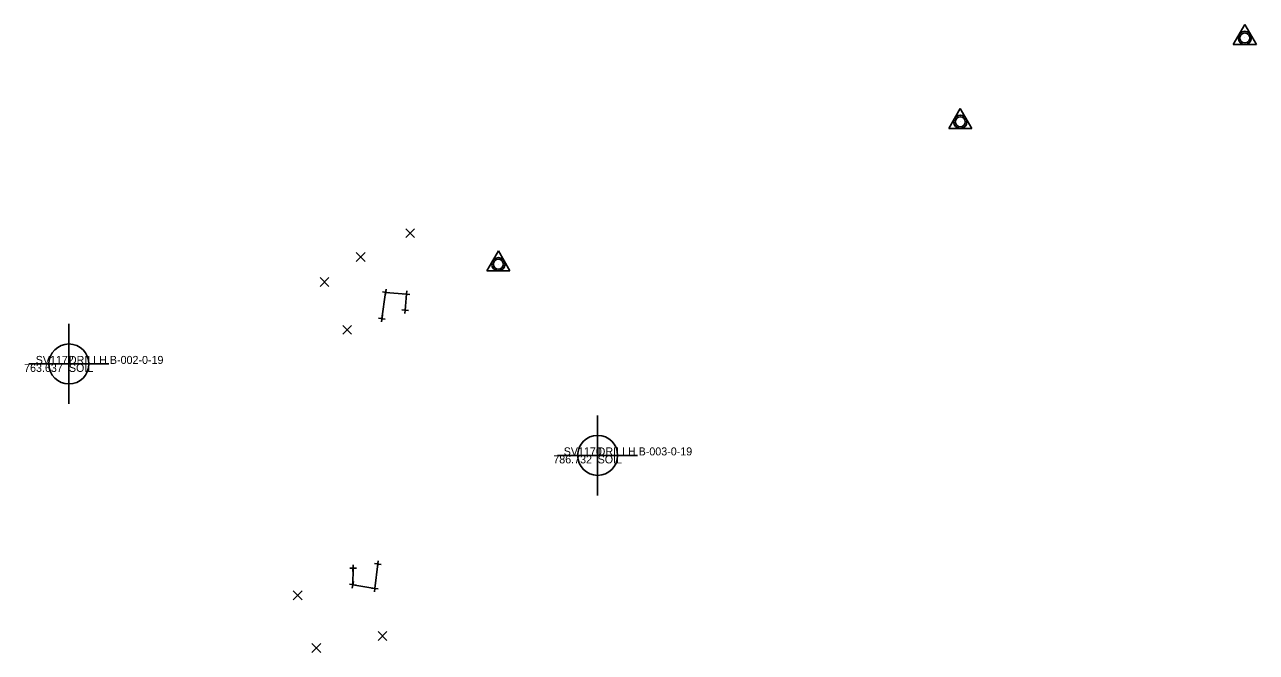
# Model space of a CAD drawing. Extents: x 1543088 to 1543675, y 586989 to 588001.
# Drawn here: x 1543273.7 to 1543458.4, y 587383.2 to 587477.5 of the extents above; entities that cross this region are included whole.
import ezdxf

# ---------------------------------------------------------------- set-up
doc = ezdxf.new("R2010")
doc.units = 0
for name, color, linetype in [('GT_Project_Soil_Boring', 7, 'Continuous'), ('SV_Control_Point', 7, 'Continuous'), ('SV_X_Break_Lines', 7, 'Continuous'), ('SV_X_Control_Cells_Found', 7, 'Continuous'), ('SV_X_Random_Point', 7, 'Continuous'), ('SV_X_Shot_Marker', 7, 'Continuous'), ('SV_X_Text_Comment', 7, 'Continuous'), ('SV_X_Text_Description', 7, 'Continuous'), ('SV_X_Text_Elevation', 7, 'Continuous'), ('SV_X_Text_Name', 7, 'Continuous')]:
    doc.layers.add(name, color=color, linetype=linetype)

msp = doc.modelspace()

# ---------------------------------------------------------------- linework, layer by layer
at = {"layer": 'GT_Project_Soil_Boring'}
for p, q in [((1543280.33, 587426.54), (1543280.33, 587432.54)), ((1543280.33, 587429.54), (1543280.33, 587426.54)), ((1543280.33, 587426.54), (1543274.33, 587426.54)), ((1543280.33, 587426.54), (1543277.33, 587426.54)), ((1543280.33, 587426.54), (1543280.33, 587420.54)), ((1543280.33, 587426.54), (1543286.33, 587426.54)), ((1543280.33, 587423.54), (1543280.33, 587426.54)), ((1543280.33, 587426.54), (1543283.33, 587426.54)), ((1543359.64, 587412.81), (1543359.64, 587418.81)), ((1543359.64, 587415.81), (1543359.64, 587412.81)), ((1543359.64, 587412.81), (1543353.64, 587412.81)), ((1543359.64, 587412.81), (1543356.64, 587412.81)), ((1543359.64, 587412.81), (1543359.64, 587406.81)), ((1543359.64, 587412.81), (1543365.64, 587412.81)), ((1543359.64, 587409.81), (1543359.64, 587412.81)), ((1543359.64, 587412.81), (1543362.64, 587412.81))]:
    msp.add_line(p, q, dxfattribs=at)
for centre in [(1543280.33, 587426.54), (1543359.64, 587412.81)]:
    msp.add_circle(centre, 3, dxfattribs=at)
for centre, start, end in [((1543280.33, 587426.54), 90, 180), ((1543280.33, 587426.54), 270, 360), ((1543359.64, 587412.81), 90, 180), ((1543359.64, 587412.81), 270, 360)]:
    msp.add_arc(centre, 3, start, end, dxfattribs=at)
at = {"layer": 'SV_Control_Point'}
for p, q in [((1543454.98, 587474.46), (1543456.72, 587477.46)), ((1543456.72, 587477.46), (1543458.45, 587474.46)), ((1543458.45, 587474.46), (1543454.98, 587474.46)), ((1543456.72, 587475.46), (1543456.72, 587475.46)), ((1543412.3, 587461.88), (1543414.04, 587464.88)), ((1543414.04, 587464.88), (1543415.77, 587461.88)), ((1543414.04, 587462.88), (1543414.04, 587462.88)), ((1543415.77, 587461.88), (1543412.3, 587461.88)), ((1543343.01, 587440.51), (1543344.75, 587443.51)), ((1543344.75, 587443.51), (1543346.48, 587440.51)), ((1543346.48, 587440.51), (1543343.01, 587440.51)), ((1543344.75, 587441.51), (1543344.75, 587441.51))]:
    msp.add_line(p, q, dxfattribs=at)
for centre in [(1543456.72, 587475.46), (1543414.04, 587462.88), (1543344.75, 587441.51)]:
    msp.add_circle(centre, 1, dxfattribs=at)
at = {"layer": 'SV_X_Break_Lines'}
for points in [[(1543327.28, 587433.35), (1543327.84, 587437.27), (1543330.96, 587436.99), (1543330.77, 587434.6)], [(1543326.67, 587396.52), (1543326.23, 587392.85), (1543322.93, 587393.4), (1543322.95, 587395.89)]]:
    msp.add_lwpolyline(points, dxfattribs=at)
at = {"layer": 'SV_X_Control_Cells_Found'}
for centre in [(1543456.72, 587475.46), (1543414.04, 587462.88), (1543344.75, 587441.51)]:
    msp.add_circle(centre, 0.75, dxfattribs=at)
at = {"layer": 'SV_X_Random_Point'}
for p, q in [((1543330.85, 587445.49), (1543332.18, 587446.83)), ((1543330.85, 587446.83), (1543332.18, 587445.49)), ((1543323.42, 587441.91), (1543324.76, 587443.25)), ((1543323.42, 587443.25), (1543324.76, 587441.91)), ((1543318, 587438.16), (1543319.34, 587439.49)), ((1543318, 587439.49), (1543319.34, 587438.16)), ((1543321.4, 587431), (1543322.74, 587432.33)), ((1543321.4, 587432.33), (1543322.74, 587431)), ((1543313.98, 587391.16), (1543315.32, 587392.49)), ((1543313.98, 587392.49), (1543315.32, 587391.16)), ((1543326.71, 587385.03), (1543328.04, 587386.37)), ((1543326.71, 587386.37), (1543328.04, 587385.03)), ((1543316.76, 587383.25), (1543318.1, 587384.58)), ((1543316.76, 587384.58), (1543318.1, 587383.25))]:
    msp.add_line(p, q, dxfattribs=at)
at = {"layer": 'SV_X_Shot_Marker'}
for p, q in [((1543327.35, 587437.34), (1543328.34, 587437.2)), ((1543327.77, 587436.78), (1543327.91, 587437.77)), ((1543327.84, 587437.27), (1543327.84, 587437.27)), ((1543330.46, 587437.04), (1543331.45, 587436.95)), ((1543331, 587437.49), (1543330.91, 587436.49)), ((1543330.96, 587436.99), (1543330.96, 587436.99)), ((1543330.8, 587435.1), (1543330.73, 587434.1)), ((1543326.78, 587433.42), (1543327.77, 587433.28)), ((1543327.2, 587432.85), (1543327.35, 587433.84)), ((1543327.28, 587433.35), (1543327.28, 587433.35)), ((1543331.26, 587434.56), (1543330.27, 587434.64)), ((1543330.77, 587434.6), (1543330.77, 587434.6)), ((1543322.94, 587395.39), (1543322.95, 587396.39)), ((1543327.16, 587396.46), (1543326.17, 587396.58)), ((1543326.72, 587397.01), (1543326.61, 587396.02)), ((1543326.67, 587396.52), (1543326.67, 587396.52)), ((1543322.45, 587395.89), (1543323.45, 587395.89)), ((1543322.95, 587395.89), (1543322.95, 587395.89)), ((1543323.42, 587393.32), (1543322.43, 587393.48)), ((1543322.84, 587392.9), (1543323.01, 587393.89)), ((1543322.93, 587393.4), (1543322.93, 587393.4)), ((1543326.73, 587392.79), (1543325.73, 587392.91)), ((1543326.29, 587393.35), (1543326.17, 587392.35)), ((1543326.23, 587392.85), (1543326.23, 587392.85))]:
    msp.add_line(p, q, dxfattribs=at)

# ---------------------------------------------------------------- texts
at = {"layer": 'SV_X_Text_Comment'}
for p in [(1543280.33, 587425.34), (1543359.64, 587411.61)]:
    msp.add_text('SOIL', height=1.2, dxfattribs=at).set_placement(p)
at = {"layer": 'SV_X_Text_Description'}
for s, p in [('DRILLH B-002-0-19', (1543280.33, 587426.54)), ('DRILLH B-003-0-19', (1543359.64, 587412.81))]:
    msp.add_text(s, height=1.2, dxfattribs=at).set_placement(p)
at = {"layer": 'SV_X_Text_Elevation'}
for s, p in [('763.637', (1543273.61, 587425.34)), ('786.732', (1543352.99, 587411.61))]:
    msp.add_text(s, height=1.2, dxfattribs=at).set_placement(p)
at = {"layer": 'SV_X_Text_Name'}
for s, p in [('SV1172', (1543275.35, 587426.54)), ('SV1170', (1543354.55, 587412.81))]:
    msp.add_text(s, height=1.2, dxfattribs=at).set_placement(p)

doc.saveas('drawing.dxf')
